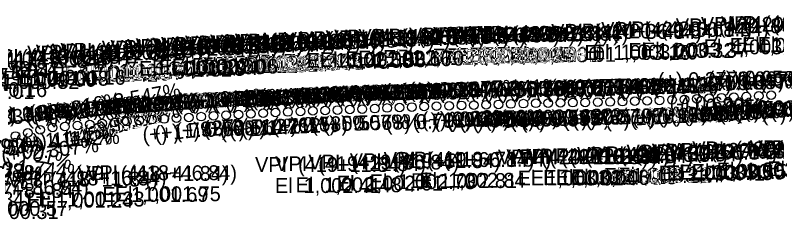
# Model space of a CAD drawing. Extents: x 16972137 to 16976737, y 12558490 to 12559551.
# Drawn here: x 16976174.7 to 16976482, y 12558906.3 to 12558989.7 of the extents above; entities that cross this region are included whole.
import ezdxf

# ---------------------------------------------------------------- set-up
doc = ezdxf.new("R2010")
doc.units = 0
doc.layers.add('RD_DDB_GradeTX', color=7, linetype='Continuous')
doc.layers.add('RD_DDB_PI', color=7, linetype='Continuous')

msp = doc.modelspace()

# ---------------------------------------------------------------- linework, layer by layer
at = {"layer": 'RD_DDB_PI'}
for centre in [(16976414.74, 12558954.64), (16976419.74, 12558954.78), (16976424.74, 12558954.95), (16976429.74, 12558955.13), (16976434.74, 12558955.3), (16976439.74, 12558955.47), (16976444.74, 12558955.67), (16976449.74, 12558955.93), (16976454.74, 12558956.15), (16976459.74, 12558956.36), (16976464.74, 12558956.58), (16976469.74, 12558956.79), (16976474.74, 12558957.09), (16976479.74, 12558957.39), (16976309.74, 12558951.58), (16976314.74, 12558951.7), (16976319.74, 12558951.96), (16976324.74, 12558952.21), (16976329.74, 12558952.38), (16976334.74, 12558952.6), (16976339.74, 12558952.81), (16976344.74, 12558952.94), (16976349.74, 12558953.11), (16976354.74, 12558953.26), (16976359.74, 12558953.39), (16976364.74, 12558953.53), (16976369.74, 12558953.68), (16976374.74, 12558953.83), (16976379.74, 12558953.96), (16976384.74, 12558954.1), (16976389.74, 12558954.2), (16976394.74, 12558954.3), (16976399.74, 12558954.37), (16976404.74, 12558954.44), (16976409.74, 12558954.53), (16976249.74, 12558948.71), (16976254.74, 12558949.02), (16976259.74, 12558949.32), (16976264.74, 12558949.59), (16976269.74, 12558949.87), (16976274.74, 12558950.12), (16976279.74, 12558950.37), (16976284.74, 12558950.61), (16976289.74, 12558950.83), (16976294.74, 12558951.03), (16976299.74, 12558951.2), (16976304.74, 12558951.38), (16976204.74, 12558945.49), (16976209.74, 12558945.94), (16976214.74, 12558946.4), (16976219.74, 12558946.8), (16976224.74, 12558947.16), (16976229.74, 12558947.51), (16976234.74, 12558947.79), (16976239.74, 12558948.07), (16976244.74, 12558948.39), (16976184.74, 12558943.43), (16976189.74, 12558944.31), (16976194.74, 12558944.71), (16976199.74, 12558945.1), (16976174.74, 12558940.88), (16976179.74, 12558942.15)]:
    msp.add_circle(centre, 1.75, dxfattribs=at)

# ---------------------------------------------------------------- texts
at = {"layer": 'RD_DDB_GradeTX'}
for s, rotation, p in [('(+) 1.124%', 3.2161, (16976431.86, 12558957.76)), ('(+) 0.277%', 0.7937, (16976434.06, 12558960.44)), ('(+) 0.684%', 1.9574, (16976448.86, 12558958.79)), ('(+) 0.657%', 1.8825, (16976453.92, 12558958.93)), ('(+) 0.067%', 0.1931, (16976454.14, 12558960.91)), ('(-) 0.056%', 359.8391, (16976458.75, 12558961.3)), ('(+) 0.863%', 2.4706, (16976468.41, 12558959.74)), ('(+) 0.851%', 2.4373, (16976475.13, 12558960.02)), ('(+) 0.400%', 1.1454, (16976323.81, 12558955.88)), ('(+) 0.391%', 1.1187, (16976330.17, 12558956.04)), ('(+) 0.284%', 0.8126, (16976333.58, 12558956.43)), ('(+) 0.977%', 2.7964, (16976339.28, 12558955.92)), ('(+) 0.712%', 2.038, (16976345.33, 12558955.94)), ('(+) 0.841%', 2.4083, (16976355.36, 12558956.47)), ('(+) 0.535%', 1.5325, (16976358.12, 12558956.3)), ('(+) 0.736%', 2.1075, (16976363.79, 12558955.71)), ('(+) 0.586%', 1.6795, (16976368.64, 12558956.67)), ('(+) 0.684%', 1.9574, (16976368.91, 12558956.05)), ('(+) 0.507%', 1.4514, (16976373.83, 12558956.74)), ('(+) 1.022%', 2.9245, (16976384.85, 12558955.62)), ('(+) 0.863%', 2.4706, (16976388.49, 12558956.29)), ('(+) 0.572%', 1.6372, (16976388.58, 12558957.22)), ('(+) 0.551%', 1.5767, (16976395.06, 12558957.39)), ('(+) 0.548%', 1.5691, (16976398.65, 12558957.48)), ('(+) 0.400%', 1.1454, (16976403.79, 12558957.48)), ('(+) 0.391%', 1.1187, (16976410.15, 12558957.6)), ('(+) 0.284%', 0.8126, (16976413.57, 12558957.57)), ('(+) 1.211%', 3.465, (16976418.39, 12558956.69)), ('(+) 0.268%', 0.7673, (16976418.58, 12558957.62)), ('(+) 1.242%', 3.5532, (16976424.98, 12558956.99)), ('(+) 3.547%', 10.0575, (16976202.92, 12558949.7)), ('(+) 1.611%', 4.6059, (16976238.5, 12558951.32)), ('(+) 1.432%', 4.0959, (16976239.71, 12558951.24)), ('(+) 0.792%', 2.2674, (16976243.85, 12558951.97)), ('(+) 1.398%', 3.9989, (16976244.95, 12558951.58)), ('(+) 1.117%', 3.1973, (16976253.79, 12558951.85)), ('(+) 1.033%', 2.9562, (16976254.73, 12558951.61)), ('(+) 0.977%', 2.7964, (16976259.38, 12558952.02)), ('(+) 1.271%', 3.6374, (16976266.87, 12558952.8)), ('(+) 0.850%', 2.4346, (16976268.55, 12558952.79)), ('(+) 1.245%', 3.5625, (16976269.93, 12558952.97)), ('(+) 0.841%', 2.4083, (16976275.44, 12558953.11)), ('(+) 1.191%', 3.407, (16976278.6, 12558953.45)), ('(+) 1.104%', 3.1607, (16976281.96, 12558953.55)), ('(+) 0.690%', 1.9757, (16976283.91, 12558953.84)), ('(+) 1.100%', 3.147, (16976286.85, 12558953.81)), ('(+) 0.586%', 1.6795, (16976288.68, 12558954.32)), ('(+) 1.015%', 2.9063, (16976291.75, 12558953.99)), ('(+) 0.983%', 2.8136, (16976293.39, 12558954.04)), ('(+) 0.953%', 2.7275, (16976298.28, 12558954.25)), ('(+) 0.620%', 1.7751, (16976303.56, 12558954.63)), ('(+) 0.915%', 2.619, (16976305.23, 12558954.55)), ('(+) 0.572%', 1.6372, (16976308.62, 12558954.94)), ('(+) 0.768%', 2.1989, (16976309.02, 12558954.58)), ('(+) 0.703%', 2.0127, (16976313.62, 12558954.69)), ('(+) 0.551%', 1.5767, (16976315.1, 12558955.19)), ('(+) 0.548%', 1.5691, (16976318.68, 12558955.29)), ('(+) 0.698%', 1.9992, (16976318.86, 12558954.87)), ('(+) 0.514%', 1.4734, (16976330.31, 12558955.11)), ('(+) 3.916%', 11.0782, (16976179.37, 12558945.29)), ('(+) 3.025%', 8.6021, (16976182.43, 12558945.08)), ('(+) 2.990%', 8.5027, (16976188.09, 12558945.9)), ('(+) 1.245%', 3.5625, (16976190.09, 12558948)), ('(+) 1.191%', 3.407, (16976198.75, 12558948.69)), ('(+) 1.104%', 3.1607, (16976202.09, 12558949.14)), ('(+) 1.100%', 3.147, (16976206.97, 12558949.42)), ('(+) 1.574%', 4.4998, (16976210.39, 12558948.95)), ('(+) 1.015%', 2.9063, (16976211.86, 12558949.93)), ('(+) 0.983%', 2.8136, (16976213.49, 12558950.12)), ('(+) 1.566%', 4.4779, (16976215.21, 12558949.32)), ('(+) 0.953%', 2.7275, (16976218.37, 12558950.45)), ('(+) 1.559%', 4.4561, (16976219.98, 12558949.69)), ('(+) 0.915%', 2.619, (16976225.32, 12558950.89)), ('(+) 0.768%', 2.1989, (16976229.08, 12558951.51)), ('(+) 0.703%', 2.0127, (16976233.67, 12558951.88)), ('(-) 0.690%', 358.0253, (16976438.7, 12558951.45)), ('(-) 0.325%', 359.0691, (16976442.95, 12558950.19)), ('(+) 1.611%', 4.6059, (16976158.77, 12558944.9)), ('(+) 1.432%', 4.0959, (16976159.93, 12558945.52)), ('(+) 1.398%', 3.9989, (16976165.16, 12558946)), ('(+) 1.276%', 3.6497, (16976180.51, 12558947.3)), ('(+) 1.271%', 3.6374, (16976187.04, 12558947.73)), ('(+) 5.113%', 14.3396, (16976203.18, 12558938.85)), ('(+) 1.196%', 3.4227, (16976422.93, 12558944.98)), ('(+) 0.580%', 1.6604, (16976433.87, 12558946.19)), ('(+) 0.665%', 1.9052, (16976439.14, 12558946.42)), ('(+) 0.736%', 2.1075, (16976444.17, 12558946.66)), ('(+) 0.045%', 0.1295, (16976448.76, 12558948.96)), ('(+) 0.835%', 2.3896, (16976458.68, 12558947.25)), ('(-) 0.088%', 359.7485, (16976463.7, 12558949.38)), ('(+) 1.022%', 2.9245, (16976465.35, 12558947.72)), ('(+) 0.248%', 0.709, (16976468.74, 12558948.34)), ('(+) 0.751%', 2.1499, (16976475.95, 12558946.94)), ('(+) 0.870%', 2.4914, (16976479.41, 12558948.21)), ('(+) 1.837%', 5.2476, (16976150.39, 12558943.5)), ('(+) 5.093%', 14.2874, (16976195.08, 12558936.77)), ('(+) 0.792%', 2.2674, (16976324.26, 12558943.14)), ('(+) 1.033%', 2.9562, (16976335.24, 12558943.75)), ('(+) 0.268%', 0.7673, (16976338.75, 12558944.55)), ('(+) 0.392%', 1.1218, (16976343.51, 12558944.24)), ('(+) 0.403%', 1.1545, (16976348.75, 12558944.3)), ('(+) 0.850%', 2.4346, (16976348.98, 12558944.19)), ('(+) 0.580%', 1.6604, (16976353.91, 12558943.87)), ('(+) 0.665%', 1.9052, (16976359.19, 12558943.76)), ('(+) 0.690%', 1.9757, (16976364.27, 12558944.61)), ('(+) 0.657%', 1.8825, (16976374.36, 12558944.31)), ('(+) 0.835%', 2.3896, (16976378.76, 12558943.91)), ('(+) 0.568%', 1.626, (16976378.99, 12558944.93)), ('(+) 0.620%', 1.7751, (16976383.89, 12558945.12)), ('(+) 0.851%', 2.4373, (16976395.71, 12558944.62)), ('(+) 0.870%', 2.4914, (16976399.49, 12558944.73)), ('(+) 0.877%', 2.51, (16976404.78, 12558944.94)), ('(+) 1.189%', 3.4011, (16976412.81, 12558944.4)), ('(+) 0.392%', 1.1218, (16976423.5, 12558945.8)), ('(+) 0.403%', 1.1545, (16976428.74, 12558945.92)), ('(+) 1.792%', 5.1194, (16976226.29, 12558938.38)), ('(+) 1.837%', 5.2476, (16976231.13, 12558938.86)), ('(+) 0.698%', 1.9992, (16976239.33, 12558940.09)), ('(+) 0.514%', 1.4734, (16976250.64, 12558941.05)), ('(+) 1.142%', 3.2679, (16976257.4, 12558940.07)), ('(+) 1.276%', 3.6497, (16976261.1, 12558940.42)), ('(+) 0.712%', 2.038, (16976265.81, 12558941.1)), ('(+) 0.535%', 1.5325, (16976278.47, 12558942.16)), ('(+) 0.507%', 1.4514, (16976294.16, 12558942.72)), ('(+) 0.568%', 1.626, (16976299.02, 12558942.66)), ('(+) 4.146%', 11.7127, (16976177.13, 12558932.81)), ('(-) 5.001%', 345.9615, (16976160.39, 12558936.4)), ('(+) 1.117%', 3.1973, (16976174.59, 12558935.41)), ('(+) 1.142%', 3.2679, (16976177.54, 12558935.51)), ('(+) 1.559%', 4.4561, (16976141.17, 12558931.51)), ('(+) 1.792%', 5.1194, (16976146.63, 12558931.25)), ('(+) 2.307%', 6.5804, (16976169.41, 12558929.99)), ('(-) 4.814%', 346.467, (16976142.94, 12558927.59)), ('(-) 3.133%', 351.0961, (16976147.87, 12558928.07)), ('(-) 3.088%', 351.2241, (16976151.85, 12558927.49)), ('(-) 1.744%', 355.0162, (16976165.06, 12558926.41))]:
    msp.add_text(s, height=6, rotation=rotation, dxfattribs=at).set_placement(p)
at = {"layer": 'RD_DDB_PI'}
for s, p in [('VPI  (420+56.84)', (16976411.15, 12558980.93)), ('VPI  (420+61.84)', (16976417.92, 12558981.15)), ('VPI  (420+86.84)', (16976441.27, 12558982.39)), ('VPI  (420+96.84)', (16976451.39, 12558983)), ('VPI  (421+01.84)', (16976459.46, 12558983.29)), ('VPI  (421+06.84)', (16976462.92, 12558983.35)), ('VPI  (419+46.84)', (16976303.39, 12558977.81)), ('VPI  (419+56.84)', (16976313.16, 12558978.11)), ('VPI  (419+61.84)', (16976319.93, 12558978.26)), ('VPI  (419+76.84)', (16976333.57, 12558978.68)), ('VPI  (419+81.84)', (16976339.81, 12558978.83)), ('VPI  (419+86.84)', (16976343.27, 12558978.96)), ('VPI  (419+91.84)', (16976349.93, 12558979.1)), ('VPI  (419+96.84)', (16976353.39, 12558979.2)), ('VPI  (420+01.84)', (16976357.8, 12558979.3)), ('VPI  (420+06.84)', (16976361.27, 12558979.37)), ('VPI  (420+36.84)', (16976390.97, 12558980.13)), ('VPI  (420+41.84)', (16976397.92, 12558980.3)), ('VPI  (418+71.84)', (16976229.99, 12558974.59)), ('VPI  (418+76.84)', (16976233.45, 12558974.87)), ('VPI  (418+81.84)', (16976239.69, 12558975.12)), ('VPI  (418+86.84)', (16976243.16, 12558975.37)), ('VPI  (418+91.84)', (16976249.81, 12558975.61)), ('VPI  (418+96.84)', (16976253.27, 12558975.83)), ('VPI  (419+01.84)', (16976259.81, 12558976.03)), ('VPI  (419+06.84)', (16976263.27, 12558976.2)), ('VPI  (419+16.84)', (16976274.93, 12558976.58)), ('VPI  (419+26.84)', (16976283.04, 12558976.96)), ('VPI  (419+31.84)', (16976289.51, 12558977.21)), ('VPI  (419+41.84)', (16976299.93, 12558977.6)), ('El  1,003.79', (16976468.05, 12558974.79)), ('El  1,003.81', (16976474.29, 12558974.85)), ('VPI  (418+26.84)', (16976182.92, 12558971.8)), ('VPI  (418+31.84)', (16976189.4, 12558972.16)), ('VPI  (418+36.84)', (16976192.86, 12558972.51)), ('VPI  (418+51.84)', (16976209.57, 12558973.39)), ('VPI  (418+56.84)', (16976213.04, 12558973.71)), ('VPI  (418+61.84)', (16976219.81, 12558974.02)), ('VPI  (418+66.84)', (16976223.27, 12558974.32)), ('El  1,003.16', (16976404.41, 12558971.63)), ('El  1,003.20', (16976407.4, 12558971.8)), ('El  1,003.32', (16976422.13, 12558972.43)), ('El  1,003.37', (16976427.64, 12558972.65)), ('El  1,003.62', (16976452.55, 12558973.89)), ('El  1,003.74', (16976463.05, 12558974.5)), ('VPI  (417+91.84)', (16976150.11, 12558968.43)), ('VPI  (417+96.84)', (16976153.57, 12558969.31)), ('VPI  (418+01.84)', (16976159.69, 12558969.71)), ('VPI  (418+06.84)', (16976163.16, 12558970.1)), ('VPI  (418+21.84)', (16976179.46, 12558971.4)), ('El  1,002.53', (16976292.31, 12558968.46)), ('El  1,002.58', (16976297.61, 12558968.71)), ('El  1,002.66', (16976307.93, 12558969.1)), ('El  1,002.70', (16976312.99, 12558969.31)), ('El  1,002.76', (16976323.11, 12558969.61)), ('El  1,002.79', (16976328.11, 12558969.76)), ('El  1,002.87', (16976342.99, 12558970.18)), ('El  1,002.90', (16976347.81, 12558970.33)), ('El  1,002.93', (16976352.55, 12558970.46)), ('El  1,002.96', (16976357.93, 12558970.6)), ('El  1,002.98', (16976362.84, 12558970.7)), ('El  1,003.00', (16976367.64, 12558970.8)), ('El  1,003.01', (16976374.29, 12558970.87)), ('El  1,001.94', (16976229.82, 12558965.52)), ('El  1,002.00', (16976232.69, 12558965.82)), ('El  1,002.06', (16976237.81, 12558966.09)), ('El  1,002.11', (16976246, 12558966.37)), ('El  1,002.16', (16976249.47, 12558966.62)), ('El  1,002.21', (16976254.11, 12558966.87)), ('El  1,002.26', (16976257.58, 12558967.11)), ('El  1,002.30', (16976262.4, 12558967.33)), ('El  1,002.34', (16976267.52, 12558967.53)), ('El  1,002.38', (16976272.43, 12558967.7)), ('El  1,002.45', (16976282.72, 12558968.08)), ('VPI  (417+66.84)', (16976123.57, 12558963.39)), ('VPI  (417+71.84)', (16976130.28, 12558964.37)), ('VPI  (417+76.84)', (16976133.75, 12558965.13)), ('El  1,001.42', (16976189.5, 12558962.9)), ('El  1,001.50', (16976194.47, 12558963.3)), ('El  1,001.57', (16976199.76, 12558963.66)), ('El  1,001.64', (16976204.82, 12558964.01)), ('El  1,001.82', (16976219.38, 12558964.89)), ('El  1,001.88', (16976224.61, 12558965.21)), ('El  1,000.82', (16976157.72, 12558959.93)), ('El  1,001.00', (16976164.58, 12558960.81)), ('El  1,001.08', (16976169.61, 12558961.21)), ('El  1,001.16', (16976176.36, 12558961.6)), ('El  1,000.16', (16976144.7, 12558956.63)), ('El  1,000.01', (16976139.58, 12558955.87)), ('VPI  (420+71.84)', (16976428.1, 12558931.58)), ('VPI  (420+76.84)', (16976431.56, 12558931.79)), ('VPI  (420+81.84)', (16976437.8, 12558932.09)), ('VPI  (420+91.84)', (16976447.92, 12558932.69)), ('VPI  (421+11.84)', (16976471.11, 12558933.18)), ('VPI  (421+16.84)', (16976474.57, 12558933.1)), ('VPI  (421+21.84)', (16976479.22, 12558933.11)), ('VPI  (419+71.84)', (16976330.11, 12558928.53)), ('VPI  (420+11.84)', (16976369.46, 12558929.44)), ('VPI  (420+16.84)', (16976372.92, 12558929.53)), ('VPI  (420+21.84)', (16976377.57, 12558929.64)), ('VPI  (420+26.84)', (16976381.03, 12558929.78)), ('VPI  (420+31.84)', (16976387.51, 12558929.95)), ('VPI  (420+46.84)', (16976401.39, 12558930.47)), ('VPI  (420+51.84)', (16976407.68, 12558930.67)), ('VPI  (420+66.84)', (16976421.39, 12558931.36)), ('VPI  (419+11.84)', (16976271.46, 12558926.38)), ('VPI  (419+21.84)', (16976279.57, 12558926.7)), ('VPI  (419+36.84)', (16976292.98, 12558927.38)), ('VPI  (419+51.84)', (16976309.69, 12558927.94)), ('VPI  (419+66.84)', (16976323.39, 12558928.39)), ('VPI  (418+41.84)', (16976199.81, 12558922.79)), ('VPI  (418+46.84)', (16976203.27, 12558923.07)), ('El  1,003.41', (16976434.41, 12558922.86)), ('El  1,003.45', (16976437.66, 12558923.08)), ('El  1,003.50', (16976442.52, 12558923.29)), ('El  1,003.56', (16976447.64, 12558923.59)), ('El  1,003.68', (16976457.78, 12558924.19)), ('El  1,003.77', (16976478.23, 12558924.68)), ('VPI  (418+11.84)', (16976171.35, 12558920.49)), ('VPI  (418+16.84)', (16976174.81, 12558920.94)), ('El  1,002.73', (16976317.72, 12558919.44)), ('El  1,002.81', (16976334.35, 12558919.89)), ('El  1,002.84', (16976337.81, 12558920.03)), ('El  1,003.02', (16976377.43, 12558920.94)), ('El  1,003.04', (16976382.75, 12558921.03)), ('El  1,003.06', (16976387.75, 12558921.14)), ('El  1,003.09', (16976392.75, 12558921.28)), ('El  1,003.13', (16976399.02, 12558921.45)), ('El  1,003.23', (16976412.13, 12558921.97)), ('El  1,003.27', (16976417.69, 12558922.17)), ('VPI  (417+86.84)', (16976143.45, 12558917.15)), ('El  1,002.41', (16976279.47, 12558917.88)), ('El  1,002.48', (16976287.84, 12558918.2)), ('El  1,002.61', (16976304.47, 12558918.88)), ('VPI  (417+81.84)', (16976139.99, 12558915.88)), ('El  1,001.69', (16976209.82, 12558914.29)), ('El  1,001.75', (16976214.79, 12558914.57)), ('VPI  (417+61.84)', (16976120.11, 12558912.36)), ('El  1,001.24', (16976179.47, 12558911.99)), ('El  1,001.33', (16976184.02, 12558912.44)), ('El  1,000.31', (16976149.29, 12558907.38)), ('El  1,000.57', (16976153.11, 12558908.65))]:
    msp.add_text(s, height=6, dxfattribs=at).set_placement(p)

doc.saveas('drawing.dxf')
